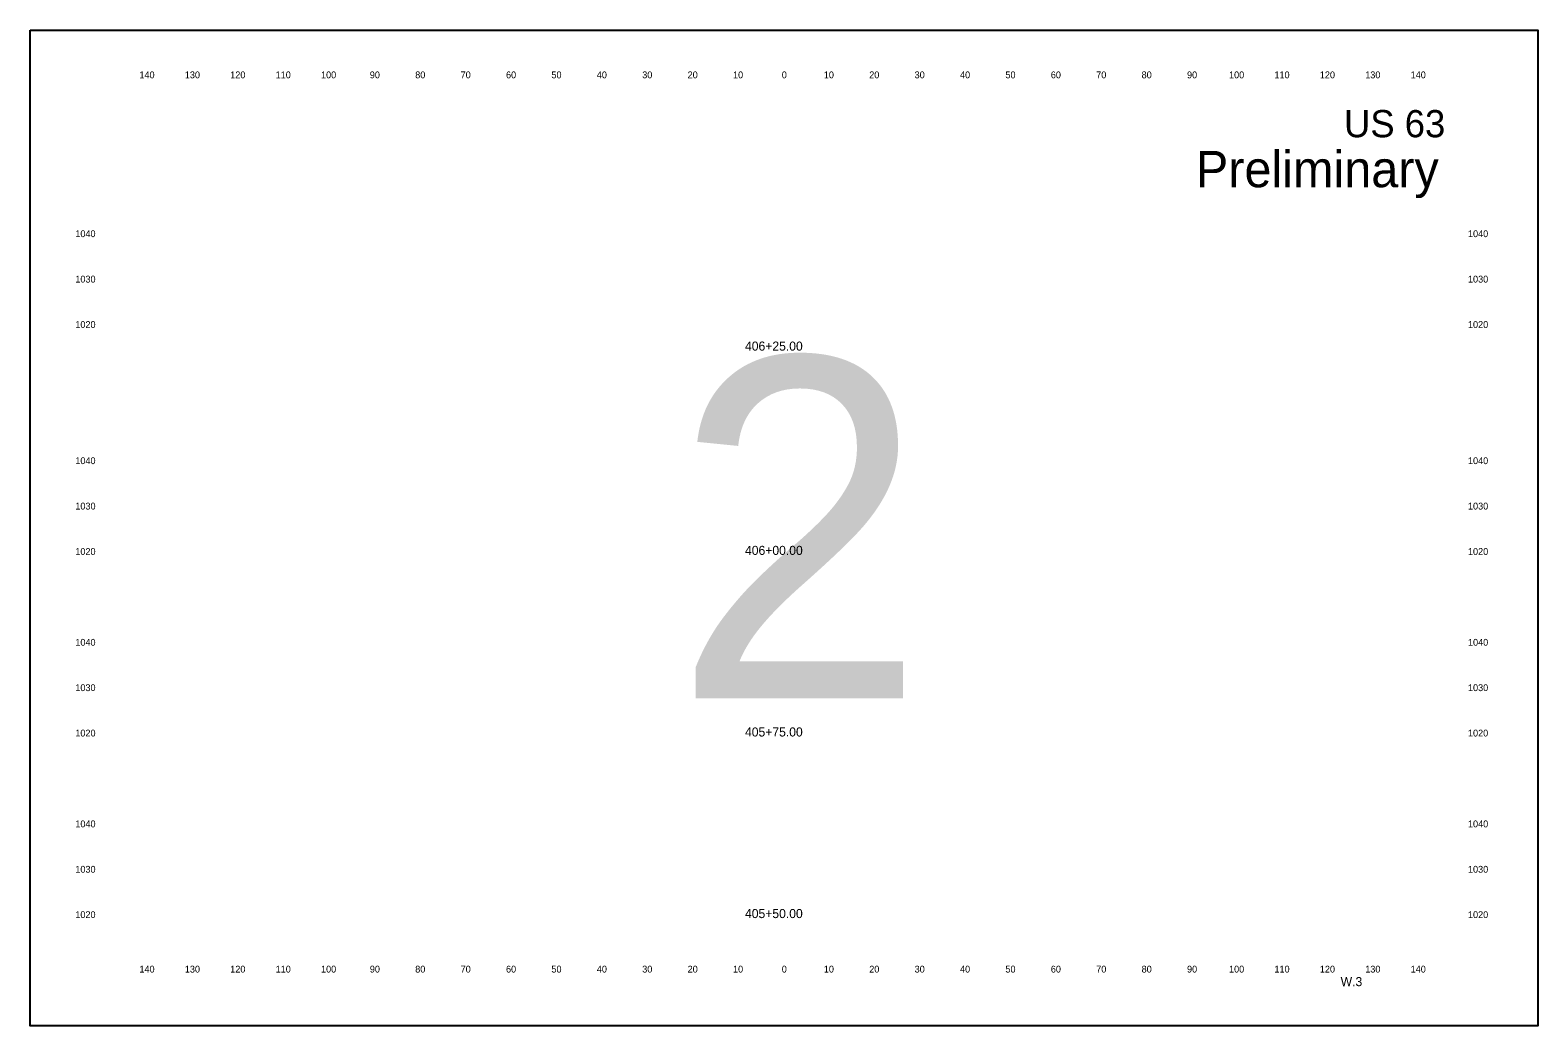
# Model space of a CAD drawing. Extents: x 10123 to 17295, y 9730 to 10181.
# Drawn here: x 10483.2 to 10815.3, y 9730.3 to 9949.6 of the extents above; entities that cross this region are included whole.
import ezdxf

# ---------------------------------------------------------------- set-up
doc = ezdxf.new("R2010")
doc.units = 0
for name, color, linetype in [('dsnTextCpn', 7, 'Continuous'), ('dsnTextCpnTitleSheetLocDesc', 7, 'Continuous'), ('dsnTextCpnTitleSheetPIN', 7, 'Continuous'), ('dsnTextCpnTitleSheetWorkType', 7, 'Continuous')]:
    doc.layers.add(name, color=color, linetype=linetype)

msp = doc.modelspace()

# ---------------------------------------------------------------- linework, layer by layer
at = {"layer": 'dsnTextCpnTitleSheetWorkType'}
msp.add_lwpolyline([(10483.21, 9949.6), (10815.29, 9949.6), (10815.29, 9730.26), (10483.21, 9730.26)], close=True, dxfattribs=at)

# ---------------------------------------------------------------- texts
at = {"layer": 'dsnTextCpn'}
for s, height, p in [('140', 1.5, (10507.27, 9939)), ('130', 1.5, (10517.27, 9939)), ('120', 1.5, (10527.27, 9939)), ('110', 1.5, (10537.27, 9939)), ('100', 1.5, (10547.27, 9939)), ('90', 1.5, (10558.02, 9939)), ('80', 1.5, (10568.02, 9939)), ('70', 1.5, (10578.02, 9939)), ('60', 1.5, (10588.02, 9939)), ('50', 1.5, (10598.02, 9939)), ('40', 1.5, (10608.02, 9939)), ('30', 1.5, (10618.02, 9939)), ('20', 1.5, (10628.02, 9939)), ('10', 1.5, (10638.02, 9939)), ('0', 1.5, (10648.76, 9939)), ('0', 1.5, (10648.76, 9939)), ('10', 1.5, (10658.02, 9939)), ('20', 1.5, (10668.02, 9939)), ('30', 1.5, (10678.02, 9939)), ('40', 1.5, (10688.02, 9939)), ('50', 1.5, (10698.02, 9939)), ('60', 1.5, (10708.02, 9939)), ('70', 1.5, (10718.02, 9939)), ('80', 1.5, (10728.02, 9939)), ('90', 1.5, (10738.02, 9939)), ('100', 1.5, (10747.27, 9939)), ('110', 1.5, (10757.27, 9939)), ('120', 1.5, (10767.27, 9939)), ('130', 1.5, (10777.27, 9939)), ('140', 1.5, (10787.27, 9939)), ('US 63', 6, (10772.6, 9926)), ('1040', 1.5, (10493.15, 9904)), ('1040', 1.5, (10799.9, 9904)), ('1030', 1.5, (10493.15, 9894)), ('1030', 1.5, (10799.9, 9894)), ('1020', 1.5, (10493.15, 9884)), ('1020', 1.5, (10799.9, 9884)), ('406+25.00', 2, (10640.66, 9879)), ('1040', 1.5, (10493.15, 9854)), ('1040', 1.5, (10799.9, 9854)), ('1030', 1.5, (10493.15, 9844)), ('1030', 1.5, (10799.9, 9844)), ('1020', 1.5, (10493.15, 9834)), ('406+00.00', 2, (10640.66, 9834)), ('1020', 1.5, (10799.9, 9834)), ('1040', 1.5, (10493.15, 9814)), ('1040', 1.5, (10799.9, 9814)), ('1030', 1.5, (10493.15, 9804)), ('1030', 1.5, (10799.9, 9804)), ('1020', 1.5, (10493.15, 9794)), ('405+75.00', 2, (10640.66, 9794)), ('1020', 1.5, (10799.9, 9794)), ('1040', 1.5, (10493.15, 9774)), ('1040', 1.5, (10799.9, 9774)), ('1030', 1.5, (10493.15, 9764)), ('1030', 1.5, (10799.9, 9764)), ('1020', 1.5, (10493.15, 9754)), ('405+50.00', 2, (10640.66, 9754)), ('1020', 1.5, (10799.9, 9754)), ('140', 1.5, (10507.27, 9742)), ('130', 1.5, (10517.27, 9742)), ('120', 1.5, (10527.27, 9742)), ('110', 1.5, (10537.27, 9742)), ('100', 1.5, (10547.27, 9742)), ('90', 1.5, (10558.02, 9742)), ('80', 1.5, (10568.02, 9742)), ('70', 1.5, (10578.02, 9742)), ('60', 1.5, (10588.02, 9742)), ('50', 1.5, (10598.02, 9742)), ('40', 1.5, (10608.02, 9742)), ('30', 1.5, (10618.02, 9742)), ('20', 1.5, (10628.02, 9742)), ('10', 1.5, (10638.02, 9742)), ('0', 1.5, (10648.76, 9742)), ('0', 1.5, (10648.76, 9742)), ('10', 1.5, (10658.02, 9742)), ('20', 1.5, (10668.02, 9742)), ('30', 1.5, (10678.02, 9742)), ('40', 1.5, (10688.02, 9742)), ('50', 1.5, (10698.02, 9742)), ('60', 1.5, (10708.02, 9742)), ('70', 1.5, (10718.02, 9742)), ('80', 1.5, (10728.02, 9742)), ('90', 1.5, (10738.02, 9742)), ('100', 1.5, (10747.27, 9742)), ('110', 1.5, (10757.27, 9742)), ('120', 1.5, (10767.27, 9742)), ('130', 1.5, (10777.27, 9742)), ('140', 1.5, (10787.27, 9742))]:
    msp.add_text(s, height=height, dxfattribs=at).set_placement(p)
at = {"layer": 'dsnTextCpnTitleSheetLocDesc'}
msp.add_text('Preliminary', height=8, dxfattribs=at).set_placement((10739.97, 9915))
at = {"layer": 'dsnTextCpnTitleSheetPIN'}
msp.add_text('W.3', height=2, dxfattribs=at).set_placement((10771.86, 9739))
at = {"layer": 'dsnTextCpnTitleSheetWorkType'}
msp.add_text('2', height=75, dxfattribs=at).set_placement((10624.72, 9802.43))

doc.saveas('drawing.dxf')
